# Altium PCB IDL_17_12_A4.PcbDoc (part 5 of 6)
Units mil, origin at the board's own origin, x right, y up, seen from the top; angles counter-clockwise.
Board outline 3172.06 x 10350 mil, 6 copper layers (Top Signal, Mid Signal, 3.3 Volt, GND, 5 Volt, Bot Signal), stack 122.8 mil thick; 332 components, 120 nets, 1937 pads, 197 vias.
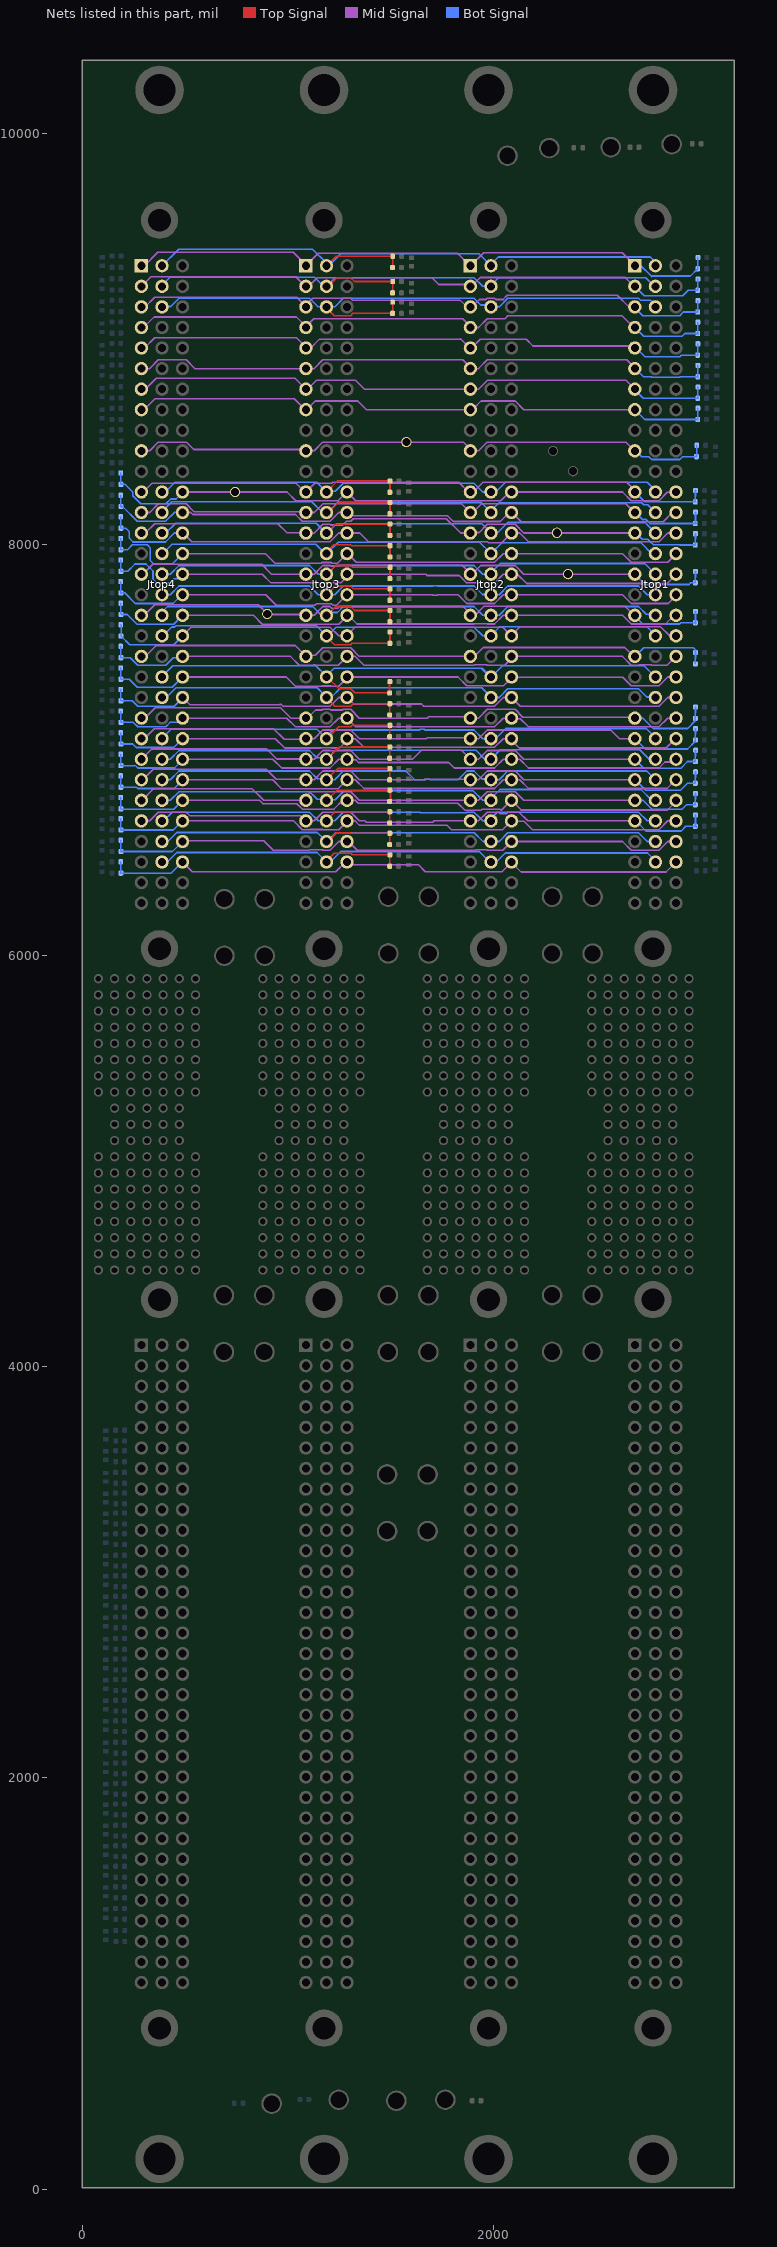
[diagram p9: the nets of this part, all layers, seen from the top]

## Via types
v1: diameter 25.59, hole 12, Top Signal to Bot Signal, 197 vias

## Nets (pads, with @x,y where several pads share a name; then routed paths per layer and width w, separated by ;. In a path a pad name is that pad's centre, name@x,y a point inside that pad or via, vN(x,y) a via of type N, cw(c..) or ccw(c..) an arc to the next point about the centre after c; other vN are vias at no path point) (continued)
JT3: Jtop1.A28 Jtop2.A28 Jtop3.A28 Jtop4.A28 R1R_IDL_17_12_TerA3.1 R2R_IDL_17_12_TerA3.2 | length 2896
  Mid Signal w8: Jtop4.A28@288.16,6654.97 328.09,6654.97 370.57,6697.45 505.76,6697.45 522.36,6680.84 1060,6680.84 1085.51,6655.33 Jtop3.A28@1088.16,6654.97 1128.09,6654.97 1170.57,6697.45 1305.76,6697.45 1348.24,6654.97 1375.92,6654.97 1382.07,6648.82 1705.13,6648.82 1709.63,6653.31 ; 1709.63,6654.97 Jtop2.A28@1888.16,6654.97 1928.09,6654.97 1970.57,6697.45 2025.56,6697.45 2032.55,6690.46 2063.58,6690.46 2070.57,6697.45 2125.04,6697.45 2167.52,6654.97 Jtop1.A28@2688.16,6654.97
  Bot Signal w8: Jtop1.A28@2692.51,6655.52 2741.96,6606.08 2913.68,6606.08 2936.14,6628.54 R1R_IDL_17_12_TerA3.1@2982.45,6628.54 ; R2R_IDL_17_12_TerA3.2@2983.33,6683.56 2983.33,6629.92 2983.58,6629.67 R1R_IDL_17_12_TerA3.1@2988.3,6624.96
JT4: Jtop1.A27 Jtop2.A27 Jtop3.A27 Jtop4.A27 R1R_IDL_17_12_TerA4.1 R2R_IDL_17_12_TerA4.2 | length 2901.7
  Mid Signal w8: Jtop4.A27@288.16,6754.97 286.98,6750.7 289.7,6753.42 348.47,6812.19 825.23,6812.19 882.73,6754.69 1067.76,6754.69 1078.1,6765.03 1110.52,6797.45 1305.76,6797.45 1348.24,6754.97 Jtop2.A27@1888.16,6754.97 1928.09,6754.97 1970.57,6797.45 2105.76,6797.45 2148.24,6754.97 2677.39,6754.97 2682.78,6760.35 Jtop1.A27@2684.55,6762.12
  Bot Signal w8: Jtop1.A27@2688.16,6754.97 2728.08,6754.97 2771.32,6711.73 2917.65,6711.73 ; 2917.4,6711.49 2917.65,6711.73 ; R2R_IDL_17_12_TerA4.2@2983.33,6788.56 2983.33,6760.61 2982.45,6759.73 R1R_IDL_17_12_TerA4.1@2982.45,6733.54 2939.45,6733.54 2917.65,6711.73
JT5: Jtop1.A26 Jtop2.A26 Jtop3.A26 Jtop4.A26 R1R_IDL_17_12_TerA5.1 R2R_IDL_17_12_TerA5.2 | length 2896.1
  Mid Signal w8: Jtop4.A26@288.16,6854.97 294.49,6854.97 345.59,6906.06 894.94,6906.06 943.77,6857.23 Jtop3.A26@1085.38,6857.23 ; Jtop3.A26@1088.16,6854.97 1128.09,6854.97 1170.57,6897.45 1305.76,6897.45 1348.24,6854.97 1380.4,6854.97 ; 1380.4,6855.02 1380.4,6854.97 ; Jtop2.A26@1883.24,6854.97 1880.13,6858.07 1669.4,6858.07 1666.3,6854.97 1380.4,6854.97 ; Jtop2.A26@1888.16,6854.97 1928.09,6854.97 1970.57,6897.45 2105.76,6897.45 2148.24,6854.97 Jtop1.A26@2688.16,6854.97 2688.86,6854.97 Jtop1.A26@2691.33,6857.43 ; Jtop1.A26@2685.24,6860.17 Jtop1.A26@2688.16,6860.17
  Bot Signal w8: Jtop1.A26@2690.58,6855.61 2741.45,6804.73 2910.48,6804.73 2944.28,6838.54 R1R_IDL_17_12_TerA5.1@2982.45,6838.54 2982.45,6864.73 2983.33,6865.61 R2R_IDL_17_12_TerA5.2@2983.33,6893.56
JT6: Jtop1.A25 Jtop2.A25 Jtop3.A25 Jtop4.A25 R1R_IDL_17_12_TerA6.1 R2R_IDL_17_12_TerA6.2 | length 2939.3
  Mid Signal w8: Jtop4.A25@288.16,6954.97 338.14,7004.95 897.38,7004.95 946.22,6956.12 1080.5,6956.12 1084.91,6951.71 1085.38,6951.23 Jtop3.A25@1086.39,6952.59 ; Jtop3.A25@1088.16,6954.96 Jtop3.A25@1086.39,6952.59 ; Jtop2.A25@1887.34,6960.37 1890.45,6957.26 1892.74,6954.97 1928.08,6954.97 1970.57,6997.45 2105.76,6997.45 2148.24,6954.97 Jtop1.A25@2688.16,6954.97 ; Jtop2.A25@1888.16,6954.97 1844.97,6998.16 1650.22,6998.16 1607.03,6954.97 1348.24,6954.97 1305.76,6997.45 1270.57,6997.45 1268.44,6995.32 1207.88,6995.32 1205.76,6997.45 1170.57,6997.45 1128.08,6954.97 1093.64,6954.97 1091.27,6952.59 1088.16,6952.59 Jtop3.A25@1086.39,6952.59
  Bot Signal w8: Jtop1.A25@2688.16,6954.97 2731.4,6911.73 2912.48,6911.73 2944.28,6943.54 R1R_IDL_17_12_TerA6.1@2982.45,6943.54 2982.45,6969.73 2983.33,6970.61 R2R_IDL_17_12_TerA6.2@2983.33,6998.56
JT7: Jtop1.A24 Jtop2.A24 Jtop3.A24 Jtop4.A24 R1R_IDL_17_12_TerA7.1 R2R_IDL_17_12_TerA7.2 | length 2909.7
  Mid Signal w8: Jtop4.A24@288.16,7054.97 302.03,7054.97 350.96,7103.9 930.7,7103.9 982.99,7051.6 1085.95,7051.6 Jtop3.A24@1088.16,7054.97 1128.09,7054.97 1170.57,7097.45 1305.76,7097.45 1348.44,7054.77 1674.53,7054.77 1678.65,7058.88 1884.24,7058.88 Jtop2.A24@1888.16,7054.97 1928.09,7054.97 1970.57,7097.45 2570.77,7097.45 2613.25,7054.97 Jtop1.A24@2688.16,7054.97 ; Jtop1.A24@2688.16,7054.97 Jtop1.A24@2688.33,7055.09
  Bot Signal w8: Jtop1.A24@2688.16,7054.97 2738.4,7004.73 2944.28,7004.73 2982.45,7042.91 R1R_IDL_17_12_TerA7.1@2982.45,7048.54 2982.45,7074.73 2983.33,7075.61 R2R_IDL_17_12_TerA7.2@2983.33,7103.56
JT8: Jtop1.A23 Jtop2.A23 Jtop3.A23 Jtop4.A23 R1R_IDL_17_12_TerA8.1 R2R_IDL_17_12_TerA8.2 | length 2932.4
  Mid Signal w8: Jtop4.A23@288.16,7154.96 304.84,7154.96 355.11,7205.24 964.87,7205.24 1015.22,7154.89 Jtop3.A23@1088.16,7154.97 Jtop3.A23@1089.27,7154.89 ; Jtop3.A23@1090.74,7154.89 Jtop3.A23@1089.27,7154.89 ; Jtop1.A23@2688.16,7154.97 2688.98,7159.85 2688.16,7159.85 2143.35,7159.85 2105.76,7197.45 1970.57,7197.45 1928.08,7154.96 Jtop2.A23@1888.16,7154.96 1881.92,7161.2 1684.6,7161.2 1678.37,7154.96 1348.24,7154.96 1305.76,7197.45 1270.57,7197.45 1267.16,7194.04 1209.16,7194.04 1205.76,7197.45 1170.57,7197.45 1167.16,7194.04 1135.22,7194.04 1092.15,7150.97 1089.27,7148.09 Jtop3.A23@1089.27,7154.89
  Bot Signal w8: Jtop1.A23@2688.16,7154.97 2728.08,7154.97 2778.32,7104.73 2945.28,7104.73 2982.45,7141.91 R1R_IDL_17_12_TerA8.1@2982.45,7153.54 2982.45,7179.73 2983.33,7180.61 R2R_IDL_17_12_TerA8.2@2983.33,7208.56
JT9: Jtop1.A20 Jtop2.A20 Jtop3.A20 Jtop4.A20 R1R_IDL_17_12_TerA9.1 R2R_IDL_17_12_TerA9.2 | length 2907
  Mid Signal w8: Jtop4.A20@288.16,7454.97 306.48,7454.97 359.78,7508.26 1035.73,7508.26 1087.01,7456.98 Jtop3.A20@1088.16,7454.97 1095.67,7454.97 1095.67,7460.01 1133.13,7460.01 1170.57,7497.45 1305.76,7497.45 1348.24,7454.97 Jtop2.A20@1888.16,7454.97 1906.95,7454.97 1950.47,7498.48 2639.52,7498.48 2685.6,7452.4 2685.73,7452.27 Jtop1.A20@2688.16,7454.97
  Bot Signal w8: Jtop1.A20@2688.16,7454.97 2730.93,7497.73 2972.33,7497.73 2983.33,7486.73 R2R_IDL_17_12_TerA9.2@2983.33,7473.56 2983.33,7445.61 2982.45,7444.73 R1R_IDL_17_12_TerA9.1@2982.45,7418.54
JT10: AS.1 Jtop1.A18 Jtop2.A18 Jtop3.A18 Jtop4.A18 R1R_IDL_17_12_TerA10.1 R2R_IDL_17_12_TerA10.2 | length 2889.6
  Mid Signal w8: Jtop4.A18@288.16,7654.97 302.48,7654.97 353.55,7706.04 857.11,7706.04 900.92,7662.23 904.17,7658.98 1084.89,7658.98 Jtop3.A18@1086.77,7657.09 ; Jtop3.A18@1088.16,7654.97 1128.09,7654.97 1170.57,7697.45 1205.76,7697.45 1213.72,7689.48 1242.78,7689.48 1250.75,7697.45 1853.99,7697.45 Jtop2.A18@1892.32,7659.12 ; Jtop2.A18@1888.16,7654.97 1911.32,7654.97 1954.84,7698.49 2640.49,7698.49 2686.08,7652.89 2686.54,7652.44 Jtop1.A18@2688.16,7654.97
  Bot Signal w8: Jtop1.A18@2692.73,7645.68 2725.92,7612.49 2905.76,7612.49 2911.81,7618.54 R1R_IDL_17_12_TerA10.1@2982.45,7618.54 ; R1R_IDL_17_12_TerA10.1@2982.26,7613.16 2983.33,7614.22 2983.33,7618.54 R2R_IDL_17_12_TerA10.2@2983.33,7673.56
JT11: DTACK.1 Jtop1.A16 Jtop2.A16 Jtop3.A16 Jtop4.A16 R1R_IDL_17_12_TerA11.1 R2R_IDL_17_12_TerA11.2 | length 2900.5
  Mid Signal w8: Jtop4.A16@288.16,7854.97 294.33,7854.97 342.51,7903.14 873.03,7903.14 920.95,7855.23 1088.16,7855.23 Jtop3.A16@1088.67,7855.23 ; Jtop3.A16@1088.16,7854.96 1128.08,7854.96 1170.57,7897.45 1205.76,7897.45 1208.35,7894.85 1247.35,7894.85 1251.5,7899 1849.15,7899 1888.47,7859.69 Jtop2.A16@1888.16,7854.97 1889.28,7853.85 1889.28,7848.03 1889.53,7848.03 1892.31,7850.82 1938.94,7897.45 2105.76,7897.45 2148.24,7854.97 2363.44,7854.97 Jtop1.A16@2688.16,7854.97
  Bot Signal w8: Jtop1.A16@2688.16,7854.97 2738.4,7804.73 2951.28,7804.73 2960.08,7813.54 R1R_IDL_17_12_TerA11.1@2982.45,7813.54 2982.45,7839.73 2983.33,7840.61 R2R_IDL_17_12_TerA11.2@2983.33,7868.56
JT12: Jtop1.A14 Jtop2.A14 Jtop3.A14 Jtop4.A14 R1R_IDL_17_12_TerA12.1 R2R_IDL_17_12_TerA12.2 WRITE.1 | length 2922.4
  Mid Signal w8: Jtop4.A14@288.16,8054.96 307.22,8054.96 352.78,8100.52 951.76,8100.52 996.25,8056.03 Jtop3.A14@1086.28,8056.03 ; Jtop3.A14@1085.53,8054.61 Jtop3.A14@1086.28,8054.61 ; Jtop3.A14@1086.38,8056.03 Jtop3.A14@1086.28,8056.03 ; Jtop1.A14@2688.16,8054.97 2308.92,8054.97 2148.24,8054.97 2105.76,8097.45 1970.57,8097.45 1930.56,8057.44 1888.54,8057.44 Jtop2.A14@1888.16,8054.96 1887.96,8055.16 1841.08,8055.16 1771.29,8124.96 1318.23,8124.96 1305.76,8112.48 1285.6,8112.48 1267.63,8094.51 1208.69,8094.51 1205.76,8097.45 1170.57,8097.45 1127.73,8054.61 1088.16,8054.61 Jtop3.A14@1086.28,8054.61 ; Jtop3.A14@1086.28,8054.61 1086.28,8054.97 Jtop3.A14@1086.28,8056.03
  Bot Signal w8: Jtop1.A14@2688.96,8059.36 2690.75,8057.56 2723.75,8024.57 2751.44,8024.57 2771.28,8004.73 ; 2763.18,8013.08 2778.82,7997.45 2905.76,7997.45 2906.45,7996.75 R1R_IDL_17_12_TerA12.1@2982.09,7996.75 2982.09,8023.73 2982.96,8024.61 R2R_IDL_17_12_TerA12.2@2982.96,8051.77
JT13: Jtop1.A13 Jtop2.A13 Jtop3.A13 Jtop4.A13 R1R_IDL_17_12_TerA13.1 R2R_IDL_17_12_TerA13.2 | length 2885.2
  Mid Signal w8: Jtop4.A13@288.16,8154.97 328.09,8154.97 370.57,8197.45 505.76,8197.45 543.83,8159.38 Jtop3.A13@1083.49,8159.38 ; Jtop3.A13@1088.16,8154.97 1128.08,8154.97 1171.04,8197.92 1844.66,8197.92 1885.01,8157.57 Jtop2.A13@1888.16,8154.97 1899.58,8154.97 1942.53,8197.92 2643.47,8197.92 2687.3,8154.1 2690.15,8151.25 Jtop1.A13@2688.16,8154.97
  Bot Signal w8: Jtop1.A13@2687.17,8159.71 2690.04,8156.84 2726.82,8120.07 2731.78,8120.07 2733.44,8121.72 2741.73,8121.72 2761.7,8101.75 R1R_IDL_17_12_TerA13.1@2982.09,8101.75 ; R2R_IDL_17_12_TerA13.2@2982.96,8156.77 2982.96,8105.07 2984.18,8103.85 R1R_IDL_17_12_TerA13.1@2987.02,8101.01
JT14: Jtop1.A12 Jtop2.A12 Jtop3.A12 Jtop4.A12 R1R_IDL_17_12_TerA14.1 R2R_IDL_17_12_TerA14.2 | length 2954.8
  Mid Signal w8: Jtop4.A12@288.16,8254.97 296.99,8254.97 339.71,8297.68 1040.35,8297.68 1081.49,8256.55 1081.49,8254.97 Jtop3.A12@1088.16,8254.97 1130.64,8297.45 1213.36,8297.45 1218.21,8302.29 1831.29,8302.29 1878.62,8254.97 Jtop2.A12@1888.16,8254.97 1901.47,8254.97 1949.08,8302.57 2648.75,8302.57 2688.45,8262.87 2688.45,8258.73 2688.16,8258.73 2658.28,8258.73 2658.28,8254.97 Jtop1.A12@2688.16,8254.97
  Bot Signal w8: Jtop1.A12@2693.2,8255.79 2692.31,8256.68 Jtop1.A12@2688.16,8254.97 2690.57,8253.16 2736.98,8206.75 R1R_IDL_17_12_TerA14.1@2982.09,8206.75 2982.09,8233.73 2982.96,8234.61 R2R_IDL_17_12_TerA14.2@2982.96,8261.77
JT15: Jtop1.A10 Jtop2.A10 Jtop3.A10 Jtop4.A10 R1R_IDL_17_12_TerA15.1 R2R_IDL_17_12_TerA15.2 SYSCLK.1 | length 2896
  Mid Signal w8: Jtop4.A10@288.16,8454.97 328.09,8454.97 370.57,8497.45 505.76,8497.45 542.01,8461.19 1088.16,8461.19 Jtop3.A10@1091.62,8461.19 ; Jtop3.A10@1088.16,8454.97 1128.09,8454.97 1170.57,8497.45 1576.8,8497.45 1854.18,8497.45 1892.41,8459.22 Jtop2.A10@1896.66,8454.97 ; Jtop2.A10@1888.16,8454.97 Jtop2.A10@1896.66,8454.97 ; Jtop1.A10@2688.16,8454.97 2686.54,8454.87 2643.96,8497.45 1970.57,8497.45 1928.09,8454.97 Jtop2.A10@1896.66,8454.97
  Bot Signal w8: Jtop1.A10@2689.55,8459.56 2691.15,8457.96 2722.42,8426.69 2756.36,8426.69 2770.57,8412.49 2905.76,8412.49 2919.96,8426.69 R1R_IDL_17_12_TerA15.1@2988.09,8426.69 ; R1R_IDL_17_12_TerA15.1@2983.06,8427.04 2985.4,8429.38 2988.97,8432.95 R2R_IDL_17_12_TerA15.2@2988.97,8481.71
JT16: Jtop1.A8 Jtop2.A8 Jtop3.A8 Jtop4.A8 R1R_IDL_17_12_TerA16.1 R2R_IDL_17_12_TerA16.2 | length 2905.5
  Mid Signal w8: Jtop4.A8@288.16,8654.97 300.95,8654.97 354.37,8708.38 1031.35,8708.38 1082.75,8656.98 1082.75,8654.97 Jtop3.A8@1088.16,8654.97 1090.64,8654.98 1133.11,8697.45 1340.78,8697.45 1383.26,8654.97 Jtop2.A8@1888.16,8654.97 ; Jtop2.A8@1878.28,8662.46 1888.16,8662.46 1905.25,8662.46 1940.23,8697.45 2105.76,8697.45 2148.24,8654.97 Jtop1.A8@2685.63,8654.97 ; Jtop1.A8@2686.69,8653.91 Jtop1.A8@2685.63,8654.97 ; Jtop1.A8@2688.16,8654.97 Jtop1.A8@2685.63,8654.97
  Bot Signal w8: Jtop1.A8@2688.61,8654.97 2736.2,8607.39 R1R_IDL_17_12_TerA16.1@2993.79,8607.39 ; R1R_IDL_17_12_TerA16.1@2993.99,8606.13 2994.52,8606.67 2994.67,8606.82 2994.67,8607.39 R2R_IDL_17_12_TerA16.2@2994.67,8662.41
JT17: Jtop1.A7 Jtop2.A7 Jtop3.A7 Jtop4.A7 R1R_IDL_17_12_TerA17.1 R2R_IDL_17_12_TerA17.2 | length 2902.4
  Mid Signal w8: Jtop4.A7@288.16,8754.97 307.37,8754.97 360.36,8807.95 1034.91,8807.95 1086.19,8756.67 Jtop3.A7@1088.16,8754.96 1088.16,8750.34 1091.95,8750.34 1092.37,8750.76 1139.05,8797.45 1330.64,8797.45 1373.12,8754.97 Jtop2.A7@1888.16,8754.97 1928.09,8754.97 1970.57,8797.45 2645.91,8797.45 2688.28,8755.08 Jtop1.A7@2688.83,8754.52
  Bot Signal w8: Jtop1.A7@2687.7,8751.74 2729.05,8710.39 R1R_IDL_17_12_TerA17.1@2993.79,8710.39 ; Jtop1.A7@2688.16,8754.97 Jtop1.A7@2689.54,8753.59 ; R2R_IDL_17_12_TerA17.2@2994.67,8765.41 2994.67,8712.72 2995.4,8711.99 R1R_IDL_17_12_TerA17.1@2996.73,8710.66
JT18: Jtop1.A6 Jtop2.A6 Jtop3.A6 Jtop4.A6 R1R_IDL_17_12_TerA18.1 R2R_IDL_17_12_TerA18.2 | length 2898.3
  Mid Signal w8: Jtop4.A6@288.16,8854.97 328.09,8854.97 370.57,8897.45 505.76,8897.45 548.24,8854.97 1072.35,8854.97 Jtop3.A6@1080.07,8862.69 ; Jtop3.A6@1088.16,8854.97 1128.09,8854.97 1170.57,8897.45 1850.68,8897.45 1890.66,8857.46 1892.34,8855.78 Jtop2.A6@1888.16,8854.97 1928.09,8854.97 1970.57,8897.45 2648.15,8897.45 2689.39,8856.2 Jtop1.A6@2692.77,8852.82
  Bot Signal w8: Jtop1.A6@2688.16,8854.97 2690.71,8854.58 2729.9,8815.39 2767.66,8815.39 2770.57,8812.49 2905.76,8812.49 2908.66,8815.39 R1R_IDL_17_12_TerA18.1@2993.79,8815.39 ; R2R_IDL_17_12_TerA18.2@2994.67,8870.41 2994.67,8815.39 2994.67,8813.15 R1R_IDL_17_12_TerA18.1@2996.39,8811.43
JT19: Jtop1.A5 Jtop2.A5 Jtop3.A5 Jtop4.A5 R1R_IDL_17_12_TerA19.1 R2R_IDL_17_12_TerA19.2 | length 2965.7
  Mid Signal w8: Jtop4.A5@288.16,8954.96 302.98,8954.96 352.41,9004.4 1042.13,9004.4 1084.75,8961.78 1088.16,8961.78 Jtop3.A5@1088.16,8954.97 1111.23,8954.97 1154.75,8998.49 1840.54,8998.49 ; 1839.68,8999.34 1840.54,8998.49 ; Jtop2.A5@1883.28,8955.74 1840.54,8998.49 ; Jtop2.A5@1885.12,8954.23 1840.86,8998.49 1840.54,8998.49 ; Jtop2.A5@1888.16,8954.97 Jtop2.A5@1893.82,8954.97 ; Jtop2.A5@1890.63,8951.78 1890.99,8952.14 Jtop2.A5@1893.82,8954.97 ; Jtop1.A5@2689.05,8953.4 2687.82,8954.63 2677.94,8964.52 2192.44,8964.52 2159.51,8997.45 1936.3,8997.45 Jtop2.A5@1893.82,8954.97
  Bot Signal w8: Jtop1.A5@2688.16,8954.97 2689.28,8953.84 2692.51,8957.07 2737.1,8912.49 2905.76,8912.49 2913.66,8920.39 R1R_IDL_17_12_TerA19.1@2993.79,8920.39 2993.79,8946.73 2994.67,8947.61 R2R_IDL_17_12_TerA19.2@2994.67,8975.41
JT20: Jtop1.A4 Jtop2.A4 Jtop3.A4 Jtop4.A4 R1R_IDL_17_12_TerA20.1 R2R_IDL_17_12_TerA20.2 | length 2916
  Mid Signal w8: Jtop4.A4@288.16,9054.97 298.59,9054.97 349.73,9106.1 1042,9106.1 1087.97,9060.13 1125.58,9097.73 1851.15,9097.73 Jtop2.A4@1889.2,9059.69 ; Jtop3.A4@1088.16,9054.97 Jtop3.A4@1096.88,9054.97 ; Jtop2.A4@1888.16,9054.97 1889.77,9054.8 1927.92,9054.8 1970.57,9097.45 2056.22,9097.45 2070.46,9111.69 2625.92,9111.69 2682.64,9054.97 Jtop1.A4@2688.16,9054.97
  Bot Signal w8: Jtop1.A4@2688.16,9054.97 2731.4,9011.73 2917.62,9011.73 2931.28,9025.39 R1R_IDL_17_12_TerA20.1@2993.79,9025.39 ; R2R_IDL_17_12_TerA20.2@2994.67,9080.41 2994.67,9025.39 2994.67,9024.42 R1R_IDL_17_12_TerA20.1@2996.39,9022.7
JT21: Jtop1.A3 Jtop2.A3 Jtop3.A3 Jtop4.A3 R1R_IDL_17_12_TerA21.1 R2R_IDL_17_12_TerA21.2 | length 2912
  Mid Signal w8: Jtop4.A3@288.16,9154.97 305.32,9154.97 352.35,9202 1043.31,9202 1084.03,9161.27 1086.13,9161.81 1121.77,9197.45 1305.76,9197.45 1316.63,9186.57 1839.68,9186.57 1871.29,9154.97 Jtop2.A3@1888.16,9154.97 1890.17,9152.96 1894.23,9152.96 1932.41,9191.14 1964.26,9191.14 1970.57,9197.45 2005.76,9197.45 2012.06,9191.14 2046.63,9191.14 2067.57,9212.07 2602.49,9212.07 2659.6,9154.97 Jtop1.A3@2688.16,9154.97
  Bot Signal w8: Jtop1.A3@2685.32,9153.06 2685.79,9152.59 2725.9,9112.49 2905.76,9112.49 2923.66,9130.39 R1R_IDL_17_12_TerA21.1@2993.79,9130.39 ; R1R_IDL_17_12_TerA21.1@2990.99,9130.59 2992.3,9131.89 2994.67,9134.26 R2R_IDL_17_12_TerA21.2@2994.67,9185.41
JT22: Jtop1.A2 Jtop2.A2 Jtop3.A2 Jtop4.A2 R1R_IDL_17_12_TerA22.1 R2R_IDL_17_12_TerA22.2 | length 2903.5
  Mid Signal w8: Jtop4.A2@288.16,9254.97 335.03,9301.83 1038.05,9301.83 1085.34,9254.54 Jtop3.A2@1088.16,9254.97 1101.34,9254.97 1143.82,9297.45 1701.44,9297.45 1734.95,9263.94 1879.91,9263.94 1887.65,9256.2 Jtop2.A2@1888.16,9254.97 1891.1,9252.03 1936.85,9297.78 2640.99,9297.78 2683.26,9255.51 Jtop1.A2@2688.16,9254.97
  Bot Signal w8: Jtop1.A2@2688.16,9254.97 2734.4,9208.73 2921.28,9208.73 2947.94,9235.39 R1R_IDL_17_12_TerA22.1@2993.79,9235.39 2993.79,9261.73 2994.67,9262.61 R2R_IDL_17_12_TerA22.2@2994.67,9290.41
JT23: Jtop1.A1 Jtop2.A1 Jtop3.A1 Jtop4.A1 R1R_IDL_17_12_TerA23.1 R2R_IDL_17_12_TerA23.2 | length 2959.5
  Mid Signal w8: Jtop4.A1@288.16,9354.97 302.73,9354.97 368.01,9420.25 1027.26,9420.25 Jtop3.A1@1090.35,9357.16 ; Jtop3.A1@1088.16,9354.97 Jtop3.A1@1090.35,9357.16 ; Jtop3.A1@1093.28,9354.23 Jtop3.A1@1090.35,9357.16 ; Jtop2.A1@1883.61,9362.84 1877.87,9362.84 1825.25,9415.47 1148.66,9415.47 Jtop3.A1@1090.35,9357.16 ; Jtop2.A1@1888.16,9354.97 1889.13,9354.97 1952.5,9418.34 2626.1,9418.34 Jtop1.A1@2687.34,9357.1
  Bot Signal w8: Jtop1.A1@2688.16,9354.97 2717.17,9354.97 2767.13,9305 ; 2769.83,9302.3 2767.13,9305 ; R1R_IDL_17_12_TerA23.1@2989.2,9335.57 2993.91,9340.28 2994.67,9341.04 R2R_IDL_17_12_TerA23.2@2994.67,9395.41 ; R1R_IDL_17_12_TerA23.1@2993.79,9340.39 2958.4,9305 2767.13,9305
JT24: Jtop1.B30 Jtop2.B30 Jtop3.B30 Jtop4.B30 R1R_IDL_17_12_TerA24.1 R2R_IDL_17_12_TerA24.2 | length 2957.4
  Top Signal w8: Jtop3.B30@1188.16,6454.97 1184.01,6455.89 1185.62,6457.51 1225.56,6497.45 1305.76,6497.45 1313.55,6489.66 R2R_IDL_17_12_TerA24.2@1496.47,6489.66 1496.47,6438.65 1498.04,6437.08 1500.39,6434.74 R1R_IDL_17_12_TerA24.1@1495.59,6434.64
  Bot Signal w8: Jtop4.B30@388.16,6454.97 413.7,6454.97 459.99,6501.26 1142.38,6501.26 1181.3,6462.33 1181.3,6459.73 1164.28,6459.73 1164.28,6454.97 Jtop3.B30@1188.16,6454.97 1206.81,6454.97 1258.29,6506.44 1930.55,6506.44 1981.36,6455.63 1981.36,6454.97 Jtop2.B30@1988.16,6454.97 2013.92,6454.97 2057.58,6498.62 2749.38,6498.62 2788.47,6459.54 Jtop1.B30@2788.16,6454.97
JT25: Jtop1.B29 Jtop2.B29 Jtop3.B29 Jtop4.B29 R1R_IDL_17_12_TerA25.1 R2R_IDL_17_12_TerA25.2 | length 2941.6
  Top Signal w8: Jtop3.B29@1189.42,6548.4 1192.08,6551.05 1238.47,6597.45 1305.76,6597.45 1308.55,6594.66 R2R_IDL_17_12_TerA25.2@1496.47,6594.66 1496.47,6539.64 1496.47,6538.57 R1R_IDL_17_12_TerA25.1@1491.04,6533.14
  Bot Signal w8: Jtop4.B29@388.16,6554.97 416.35,6554.97 460.13,6598.74 1143.19,6598.74 1181.3,6560.63 1181.3,6554.97 Jtop3.B29@1188.16,6554.97 1191.93,6557.6 1231.77,6597.45 1907.5,6597.45 1949.98,6554.97 Jtop2.B29@1988.16,6554.97 1987.28,6555.85 Jtop2.B29@1987.28,6563.06 ; Jtop1.B29@2788.16,6554.97 2748.24,6554.97 2705.76,6597.45 2070.57,6597.45 2028.09,6554.97 1995.37,6554.97 1991.77,6558.57 Jtop2.B29@1987.28,6563.06 ; Jtop2.B29@1987.28,6563.06 1987.28,6570.93 1979.41,6570.93 Jtop2.B29@1987.28,6563.06
JT26: Jtop1.B28 Jtop2.B28 Jtop3.B28 Jtop4.B28 R1R_IDL_17_12_TerA26.1 R2R_IDL_17_12_TerA26.2 | length 2898.9
  Top Signal w8: Jtop3.B28@1185,6654.67 1186.72,6656.4 1229.98,6699.66 R2R_IDL_17_12_TerA26.2@1496.47,6699.66 1496.47,6653.18 1500.3,6649.35 R1R_IDL_17_12_TerA26.1@1503.34,6646.31
  Bot Signal w8: Jtop4.B28@394.24,6654.12 437.57,6697.45 1105.76,6697.45 1148.24,6654.97 Jtop3.B28@1188.16,6654.97 ; Jtop3.B28@1188.36,6655.78 1188.67,6655.47 1189.18,6654.97 1228.09,6654.97 1245.68,6672.56 1270.57,6697.45 1641.31,6697.45 1644.92,6693.84 1676.45,6693.84 1678.05,6695.44 1696.93,6695.44 1697.48,6694.89 1868.01,6694.89 1870.56,6697.45 1905.76,6697.45 1930.64,6672.56 1948.24,6654.97 Jtop2.B28@1988.16,6654.97 ; Jtop2.B28@1978.33,6656.61 Jtop2.B28@1982.42,6660.71 ; Jtop2.B28@1982.42,6660.71 2019.16,6697.45 2705.76,6697.45 2748.24,6654.97 Jtop1.B28@2788.16,6654.97
JT27: Jtop1.B27 Jtop2.B27 Jtop3.B27 Jtop4.B27 R1R_IDL_17_12_TerA27.1 R2R_IDL_17_12_TerA27.2 | length 2909.2
  Top Signal w8: Jtop3.B27@1193.36,6758.99 1239.03,6804.66 R2R_IDL_17_12_TerA27.2@1496.47,6804.66 1499.9,6801.23 1499.9,6752.1 R1R_IDL_17_12_TerA27.1@1495.59,6749.64
  Bot Signal w8: Jtop4.B27@388.16,6754.97 428.08,6754.97 470.57,6797.45 1105.76,6797.45 1130.64,6772.56 1142.97,6760.23 1186.28,6760.23 1186.28,6756.85 Jtop3.B27@1188.16,6754.97 1187.61,6757.6 1188.16,6757.6 1230.72,6757.6 1274.96,6801.85 1901.36,6801.85 1948.24,6754.97 Jtop2.B27@1988.16,6754.97 1988.16,6763.73 1991.13,6763.73 1991.13,6766.35 2032.17,6807.39 2718.12,6807.39 2770.55,6754.97 Jtop1.B27@2788.16,6754.97
JT28: Jtop1.B26 Jtop2.B26 Jtop3.B26 Jtop4.B26 R1R_IDL_17_12_TerA28.1 R2R_IDL_17_12_TerA28.2 | length 2917.4
  Top Signal w8: Jtop3.B26@1187.53,6860.55 1189.42,6860.09 1192.38,6859.36 1242.67,6909.66 R2R_IDL_17_12_TerA28.2@1496.47,6909.66 1496.47,6863.31 R1R_IDL_17_12_TerA28.1@1494.98,6861.82
  Bot Signal w8: Jtop4.B26@388.16,6854.97 428.08,6854.97 470.56,6897.45 1105.76,6897.45 1142.65,6860.55 Jtop3.B26@1187.53,6860.55 ; Jtop3.B26@1188.16,6854.96 1228.08,6854.96 1270.57,6897.45 1574.43,6897.45 1615.94,6855.94 1667.27,6855.94 1669.4,6858.07 1688.28,6858.07 1690.42,6855.94 1829.06,6855.94 1870.57,6897.45 1905.76,6897.45 1944.31,6858.89 Jtop2.B26@1986.65,6858.89 ; Jtop2.B26@1988.16,6854.97 2028.08,6854.97 2070.56,6897.45 2746.38,6897.45 2788.51,6855.31 Jtop1.B26@2790.76,6853.06
JT29: Jtop1.B25 Jtop2.B25 Jtop3.B25 Jtop4.B25 R1R_IDL_17_12_TerA29.1 R2R_IDL_17_12_TerA29.2 | length 2917.7
  Top Signal w8: Jtop3.B25@1188.16,6954.97 1190.41,6954.32 1248.57,7012.49 1305.76,7012.49 1307.93,7014.66 R2R_IDL_17_12_TerA29.2@1496.47,7014.66 1497.93,7012.38 1495.59,7010.05 R1R_IDL_17_12_TerA29.1@1495.59,6959.64
  Bot Signal w8: Jtop4.B25@388.16,6954.97 428.08,6954.97 470.57,6997.45 1105.76,6997.45 1141.37,6961.84 1188.16,6961.84 Jtop3.B25@1188.16,6954.97 1190.49,6954.73 1233.91,6998.16 1915.42,6998.16 1915.68,6997.9 1958.62,6954.97 Jtop2.B25@1976.28,6954.97 ; Jtop2.B25@1988.16,6954.97 Jtop2.B25@1976.28,6954.97 ; Jtop1.B25@2788.16,6954.97 2758.15,6954.97 2712.25,7000.87 2034.13,7000.87 1993.09,6959.83 1993.09,6957.73 1988.16,6957.73 1976.28,6957.73 Jtop2.B25@1976.28,6954.97
JT30: Jtop1.B24 Jtop2.B24 Jtop3.B24 Jtop4.B24 R1R_IDL_17_12_TerA30.1 R2R_IDL_17_12_TerA30.2 | length 2943.4
  Top Signal w8: Jtop3.B24@1188.16,7054.97 1188.93,7053.71 1189.17,7053.96 1247.7,7112.48 1305.76,7112.48 1312.93,7119.66 R2R_IDL_17_12_TerA30.2@1496.47,7119.66 1496.47,7064.64 1496.47,7057.67 R1R_IDL_17_12_TerA30.1@1495.96,7057.16
  Bot Signal w8: Jtop4.B24@388.16,7054.97 394.28,7061.08 394.28,7063.14 393.93,7063.14 432.04,7101.26 1141.87,7101.26 1182.42,7060.71 Jtop3.B24@1176.68,7054.97 ; Jtop3.B24@1182.42,7060.71 1218.21,7096.5 1269.62,7096.5 1270.57,7097.45 1641.99,7097.45 1644.9,7100.36 1663.78,7100.36 1666.69,7097.45 1905.76,7097.45 1948.24,7054.97 Jtop2.B24@1988.16,7054.97 2010.06,7054.97 2059.53,7104.44 2743.52,7104.44 2786.52,7061.45 2788.16,7061.45 Jtop1.B24@2788.16,7054.97 ; Jtop3.B24@1188.16,7054.97 Jtop3.B24@1176.68,7054.97 ; Jtop3.B24@1176.68,7054.97 1174.67,7054.97 1174.67,7052.96 Jtop3.B24@1176.68,7054.97
JT31: Jtop1.B22 Jtop2.B22 Jtop3.B22 Jtop4.B22 R1R_IDL_17_12_TerA31.1 R2R_IDL_17_12_TerA31.2 | length 2896.6
  Top Signal w8: Jtop3.B22@1191.39,7249.05 1227.96,7212.49 1305.76,7212.49 1317.93,7224.66 R2R_IDL_17_12_TerA31.2@1496.47,7224.66 1496.47,7171.29 1496.86,7170.9 1498.42,7169.34 R1R_IDL_17_12_TerA31.1@1495.59,7169.64
  Bot Signal w8: Jtop4.B22@388.16,7254.97 409.22,7254.97 456.12,7301.86 1143.19,7301.86 1181.3,7263.75 1181.3,7259.73 1183.39,7259.73 Jtop3.B22@1188.16,7254.97 1209.78,7254.97 1257.4,7302.58 1943.86,7302.58 1989.82,7256.62 Jtop2.B22@1990.3,7256.14 ; Jtop2.B22@1988.16,7254.97 2028.08,7254.97 2070.57,7297.45 2705.76,7297.45 2745.47,7257.73 Jtop1.B22@2784.19,7257.73
JT32: Jtop1.B21 Jtop2.B21 Jtop3.B21 Jtop4.B21 R1R_IDL_17_12_TerA32.1 R2R_IDL_17_12_TerA32.2 | length 3815.8
  Top Signal w8: Jtop3.B21@1193.62,7352.89 1249.07,7297.45 1305.76,7297.45 1325.57,7277.64 R1R_IDL_17_12_TerA32.1@1495.59,7277.64 ; R1R_IDL_17_12_TerA32.1@1495.23,7280.61 R1R_IDL_17_12_TerA32.1@1495.5,7280.89 ; R1R_IDL_17_12_TerA32.1@1498.49,7277.9 1497.17,7279.21 R1R_IDL_17_12_TerA32.1@1495.5,7280.89 ; R1R_IDL_17_12_TerA32.1@1495.5,7280.89 1493.73,7282.66 1493.73,7332.66 R2R_IDL_17_12_TerA32.2@1496.47,7332.66 1496.47,7281.85 R1R_IDL_17_12_TerA32.1@1495.5,7280.89
  Bot Signal w8: Jtop4.B21@388.16,7354.97 388.91,7358.03 441.07,7410.19 1136.17,7410.19 Jtop3.B21@1186.73,7359.63 ; Jtop3.B21@1184.83,7357.73 Jtop3.B21@1185.11,7358.01 ; Jtop3.B21@1188.16,7354.97 1188.16,7358.2 Jtop3.B21@1186.73,7359.63 ; Jtop2.B21@1988.16,7354.97 1945.68,7397.45 1940.72,7397.45 ; Jtop1.B21@2788.16,7354.97 2734.39,7408.74 2043.4,7408.74 1988.9,7354.23 1986.42,7351.75 1985.68,7352.49 1940.72,7397.45 ; Jtop3.B21@1185.11,7358.01 Jtop3.B21@1186.73,7359.63 ; Jtop3.B21@1185.11,7358.01 Jtop3.B21@1186.73,7359.63 ; Jtop3.B21@1186.73,7359.63 1224.55,7397.45 ; Jtop3.B21@1186.73,7359.63 1224.55,7397.45 ; 1224.55,7397.45 1940.72,7397.45 ; 1224.55,7397.45 1224.83,7397.73 1940.44,7397.73 1940.72,7397.45
JT33: Jtop1.B19 Jtop2.B19 Jtop3.B19 Jtop4.B19 R1R_IDL_17_12_TerA33.1 R2R_IDL_17_12_TerA33.2 | length 2902.2
  Top Signal w8: Jtop3.B19@1185.31,7554.32 1186.41,7553.22 1227.15,7512.49 1305.76,7512.49 1311.8,7518.53 R1R_IDL_17_12_TerA33.1@1496.55,7518.53 ; R1R_IDL_17_12_TerA33.1@1496.81,7521.3 1497.43,7521.91 R2R_IDL_17_12_TerA33.2@1497.43,7573.55
  Bot Signal w8: Jtop4.B19@385.95,7548.11 390.48,7552.65 435.57,7597.73 450.73,7597.73 456.58,7603.59 1139.54,7603.59 Jtop3.B19@1188.16,7554.97 ; Jtop3.B19@1190.31,7553.66 1234.09,7597.45 1905.76,7597.45 1948.24,7554.97 Jtop2.B19@1986.45,7554.97 ; Jtop2.B19@1988.16,7554.97 Jtop2.B19@1986.45,7554.97 ; Jtop1.B19@2788.16,7554.97 2788.16,7558.18 2747.86,7598.49 2029.97,7598.49 1987.3,7555.82 Jtop2.B19@1986.45,7554.97
JT34: Jtop1.B18 Jtop2.B18 Jtop3.B18 Jtop4.B18 R1R_IDL_17_12_TerA34.1 R2R_IDL_17_12_TerA34.2 | length 2934.7
  Top Signal w8: Jtop3.B18@1188.16,7654.97 1187.99,7651.61 1189.75,7653.38 1233.82,7697.45 1305.76,7697.45 1324.65,7678.55 R2R_IDL_17_12_TerA34.2@1497.43,7678.55 1497.43,7629.02 1495.92,7627.51 R1R_IDL_17_12_TerA34.1@1496.55,7623.53
  Bot Signal w8: Jtop4.B18@388.16,7654.97 373.87,7654.97 373.87,7655.93 380.53,7662.6 415.38,7697.45 1120.73,7697.45 1163.21,7654.97 Jtop3.B18@1188.16,7654.97 1196.44,7663.25 1196.44,7668.31 1241.43,7668.31 1270.57,7697.45 1905.76,7697.45 1948.24,7654.97 Jtop2.B18@1988.16,7654.97 2028.08,7654.97 2070.57,7697.45 2705.76,7697.45 2743.74,7659.47 2787.04,7659.47 Jtop1.B18@2788.16,7654.97
JT35: Jtop1.B17 Jtop2.B17 Jtop3.B17 Jtop4.B17 R1R_IDL_17_12_TerA35.1 R2R_IDL_17_12_TerA35.2 | length 2913.6
  Top Signal w8: Jtop3.B17@1187.99,7755.15 1230.28,7797.45 1305.76,7797.45 1319.65,7783.55 R2R_IDL_17_12_TerA35.2@1497.43,7783.55 1497.43,7729.54 1497.49,7729.47 R1R_IDL_17_12_TerA35.1@1501.27,7725.69
  Bot Signal w8: Jtop4.B17@388.16,7754.97 428.08,7754.97 470.56,7797.45 1105.76,7797.45 1148.24,7754.97 Jtop3.B17@1188.16,7754.96 ; Jtop3.B17@1191.89,7758.32 1188.54,7754.97 Jtop3.B17@1188.16,7754.96 ; Jtop2.B17@1988.16,7754.97 2028.08,7754.97 2070.56,7797.45 2705.76,7797.45 2748.24,7754.97 Jtop1.B17@2788.16,7754.97 2794.45,7754.97 Jtop1.B17@2796.64,7752.77 ; Jtop2.B17@1989.11,7755.94 1988.16,7755.94 1947.26,7755.94 1905.76,7797.45 1727.36,7797.45 1726.43,7798.38 1707.54,7798.38 1706.61,7797.45 1270.57,7797.45 1228.08,7754.96 Jtop3.B17@1188.16,7754.96
JT36: Jtop1.B16 Jtop2.B16 Jtop3.B16 Jtop4.B16 R1R_IDL_17_12_TerA36.1 R2R_IDL_17_12_TerA36.2 | length 2912.9
  Top Signal w8: Jtop3.B16@1189.51,7852.72 1189.31,7852.62 1185.31,7850.65 1188.89,7854.24 1232.1,7897.44 1305.76,7897.44 1314.65,7888.55 R2R_IDL_17_12_TerA36.2@1497.43,7888.55 1497.43,7833.97 R1R_IDL_17_12_TerA36.1@1501.27,7830.12
  Bot Signal w8: Jtop4.B16@392.29,7855.89 393.22,7854.97 428.09,7854.97 470.56,7897.44 1105.76,7897.44 1148.24,7854.97 Jtop3.B16@1188.16,7854.97 ; Jtop3.B16@1189.31,7852.62 1189.51,7852.72 1189.96,7853.17 1234.24,7897.45 1905.76,7897.45 1948.24,7854.97 Jtop2.B16@1988.16,7854.97 1988.16,7861.29 2033.53,7906.66 2736.47,7906.66 Jtop1.B16@2788.16,7854.97
JT37: Jtop1.B15 Jtop2.B15 Jtop3.B15 Jtop4.B15 R1R_IDL_17_12_TerA37.1 R2R_IDL_17_12_TerA37.2 | length 2897.6
  Top Signal w8: Jtop3.B15@1186.2,7960.44 1223.21,7997.45 1305.76,7997.45 1309.65,7993.55 R2R_IDL_17_12_TerA37.2@1497.43,7993.55 1497.43,7938.53 1497.43,7937.51 R1R_IDL_17_12_TerA37.1@1502.17,7932.77
  Bot Signal w8: Jtop4.B15@395.93,7959.85 437.06,8000.97 1136.17,8000.97 1182.17,7954.97 Jtop3.B15@1188.16,7954.97 ; Jtop3.B15@1193.54,7958.57 1245.79,8010.81 1932.31,8010.81 1932,8011.37 1988.16,7955.21 Jtop2.B15@1988.16,7954.97 ; Jtop2.B15@1992.11,7958.63 2040.55,8007.07 2718.66,8007.07 2770.77,7954.97 Jtop1.B15@2788.16,7954.97
JT38: Jtop1.B14 Jtop2.B14 Jtop3.B14 Jtop4.B14 R1R_IDL_17_12_TerA38.1 R2R_IDL_17_12_TerA38.2 | length 2952.3
  Top Signal w8: Jtop3.B14@1188.16,8054.97 1191.56,8057.73 1232.38,8098.55 R2R_IDL_17_12_TerA38.2@1497.43,8098.55 1497.43,8048.19 1499.32,8046.3 R1R_IDL_17_12_TerA38.1@1506.63,8038.98
  Bot Signal w8: Jtop4.B14@388.16,8054.97 406.8,8054.97 455.11,8103.28 1138.17,8103.28 Jtop3.B14@1182.31,8059.15 ; Jtop3.B14@1185.86,8048.11 1190.44,8052.69 1237.31,8099.56 1843.88,8099.56 1843.98,8099.47 1946.63,8099.47 1989.65,8056.45 Jtop2.B14@1991.14,8054.97 ; Jtop2.B14@1988.16,8054.97 Jtop2.B14@1991.14,8054.97 ; 2745.92,8097.73 2781.96,8061.69 2737.58,8106.07 2069.32,8106.07 2018.21,8054.97 Jtop2.B14@1991.14,8054.97
JT39: Jtop1.B13 Jtop2.B13 Jtop3.B13 Jtop4.B13 R1R_IDL_17_12_TerA39.1 R2R_IDL_17_12_TerA39.2 | length 2984.7
  Top Signal w8: Jtop3.B13@1197.8,8155.91 1245.45,8203.55 R2R_IDL_17_12_TerA39.2@1497.43,8203.55 ; R1R_IDL_17_12_TerA39.1@1496.55,8148.53 1496.55,8202.06 R2R_IDL_17_12_TerA39.2@1497.43,8202.94 ; R1R_IDL_17_12_TerA39.1@1496.81,8146.98 1497.43,8147.6 1497.43,8148.53 R2R_IDL_17_12_TerA39.2@1497.43,8202.94 ; R2R_IDL_17_12_TerA39.2@1502.17,8207.68 1497.73,8203.24 R2R_IDL_17_12_TerA39.2@1497.43,8202.94
  Bot Signal w8: Jtop4.B13@388.16,8154.97 388.16,8162.46 391.92,8162.46 436.05,8206.59 1117.11,8206.59 1168.74,8154.97 Jtop3.B13@1188.16,8154.97 1193.19,8154.97 1242.12,8203.89 1940.55,8203.89 1979.28,8165.16 Jtop2.B13@1979.28,8154.97 ; Jtop2.B13@1988.16,8154.97 Jtop2.B13@1979.86,8154.97 ; Jtop1.B13@2788.41,8154.95 2788.28,8155.08 2750.61,8192.75 2731.18,8192.75 2721.28,8202.65 2027.55,8202.65 1984.01,8159.12 Jtop2.B13@1979.86,8154.97 ; Jtop2.B13@1979.28,8154.97 Jtop2.B13@1979.86,8154.97 ; Jtop2.B13@1979.28,8154.97 1977.95,8154.97 1977.95,8153.05 Jtop2.B13@1979.86,8154.97
JT40: Jtop1.B12 Jtop2.B12 Jtop3.B12 Jtop4.B12 R1R_IDL_17_12_TerA40.1 R2R_IDL_17_12_TerA40.2 | length 2898.4
  Top Signal w8: Jtop3.B12@1194.23,8261.23 1241.55,8308.55 R2R_IDL_17_12_TerA40.2@1497.43,8308.55 1497.43,8253.53 1497.43,8251.69 R1R_IDL_17_12_TerA40.1@1498.6,8250.52
  Bot Signal w8: Jtop4.B12@388.16,8254.97 404.18,8254.97 451.1,8301.88 1141.18,8301.88 1185.32,8257.75 Jtop3.B12@1188.16,8254.97 1190.93,8257.73 1201.86,8257.73 1201.86,8258.24 1231.36,8258.24 1270.57,8297.45 1905.76,8297.45 1948.24,8254.97 Jtop2.B12@1988.16,8254.97 2011.99,8254.97 2058.87,8301.85 2748.02,8301.85 2787.18,8262.69 2787.18,8255.95 Jtop1.B12@2788.16,8254.97
JT41: Jtop1.B3 Jtop2.B3 Jtop3.B3 Jtop4.B3 R1R_IDL_17_12_TerA41.1 R2R_IDL_17_12_TerA41.2 | length 2957.1
  Top Signal w8: Jtop3.B3@1190.76,9147.9 1226.18,9112.49 1305.76,9112.49 1316.77,9123.5 R1R_IDL_17_12_TerA41.1@1509.6,9123.5 ; R2R_IDL_17_12_TerA41.2@1510.47,9178.52 1510.47,9128.02 R1R_IDL_17_12_TerA41.1@1512.27,9126.22
  Bot Signal w8: Jtop4.B3@388.16,9154.96 383.47,9154.96 383.47,9156.98 388.16,9156.98 430.1,9156.98 470.57,9197.45 1105.76,9197.45 1148.24,9154.97 Jtop3.B3@1188.16,9154.97 1228.08,9154.97 1270.57,9197.45 1905.76,9197.45 1939.22,9163.98 1980.81,9163.98 1980.81,9159.73 1988.16,9159.73 2004.28,9159.73 Jtop2.B3@2004.28,9154.97 ; Jtop2.B3@1988.16,9154.97 Jtop2.B3@2004.28,9154.97 ; Jtop1.B3@2788.16,9154.97 2774.28,9154.97 2774.28,9165.16 2785.54,9165.16 2762.51,9188.19 2715.01,9188.19 2705.76,9197.45 2070.57,9197.45 2028.08,9154.97 Jtop2.B3@2004.28,9154.97
JT42: Jtop1.B2 Jtop2.B2 Jtop3.B2 Jtop4.B2 R1R_IDL_17_12_TerA42.1 R2R_IDL_17_12_TerA42.2 | length 2967.9
  Top Signal w8: Jtop3.B2@1187.17,9245.83 1192.23,9250.9 1238.78,9297.45 1305.76,9297.45 1324.69,9278.52 R2R_IDL_17_12_TerA42.2@1510.47,9278.52 1510.47,9227.21 1511.89,9225.79 R1R_IDL_17_12_TerA42.1@1517.03,9220.65
  Bot Signal w8: Jtop4.B2@388.16,9254.97 403.28,9254.97 403.28,9263.59 391.37,9263.59 426.9,9299.12 1129.7,9299.12 1173.86,9254.97 1183.75,9254.97 1183.75,9250.53 Jtop3.B2@1188.16,9254.97 1230.66,9297.45 1905.76,9297.45 1948.24,9254.97 Jtop2.B2@1979.46,9254.97 ; Jtop2.B2@1988.16,9254.97 Jtop2.B2@1982.26,9254.97 ; Jtop1.B2@2788.16,9254.97 2783.67,9254.97 2741.19,9297.45 2024.74,9297.45 1985.21,9257.92 Jtop2.B2@1982.26,9254.97 ; Jtop2.B2@1979.46,9254.97 1979.46,9252.17 Jtop2.B2@1982.26,9254.97 ; Jtop2.B2@1979.46,9254.97 Jtop2.B2@1982.26,9254.97
JT43: Jtop1.B1 Jtop2.B1 Jtop3.B1 Jtop4.B1 R1R_IDL_17_12_TerA43.1 R2R_IDL_17_12_TerA43.2 | length 3629.8
  Top Signal w8: Jtop3.B1@1185.91,9351.59 1188.72,9354.4 1235.81,9401.49 R2R_IDL_17_12_TerA43.2@1510.4,9401.49 1510.4,9346.47 1510.4,9341.85 R1R_IDL_17_12_TerA43.1@1511.99,9340.26
  Bot Signal w8: Jtop4.B1@388.16,9354.97 469.19,9436 1120.49,9436 1184.98,9371.51 1184.98,9358.15 Jtop3.B1@1188.16,9354.97 1199.62,9354.97 1258.22,9413.57 1930.49,9413.57 1984.83,9359.22 2023.34,9397.73 2762.81,9397.73 2784.5,9376.04 2784.5,9354.97 Jtop1.B1@2784.5,9350.54 ; 2070.57,9397.45 2724.78,9397.45
JT44: Jtop1.C30 Jtop2.C30 Jtop3.C30 Jtop4.C30 R1R_IDL_17_12_TerA44.1 R2R_IDL_17_12_TerA44.2 | length 2891.4
  Mid Signal w8: Jtop4.C30@488.16,6454.97 490.25,6453.31 535.31,6408.25 1109.99,6408.25 1110.04,6408.21 1233.82,6408.21 1280.58,6454.97 Jtop3.C30@1284.96,6454.97 ; Jtop3.C30@1288.16,6454.97 Jtop3.C30@1284.96,6454.97 ; 1638.72,6437.63 1634.82,6441.53 1615.94,6441.53 1615.37,6440.97 1298.96,6440.97 1286.56,6453.36 Jtop3.C30@1284.96,6454.97 ; 1639.37,6438.28 1669.3,6408.36 2041.56,6408.36 Jtop2.C30@2087.27,6454.07 ; Jtop2.C30@2088.76,6452.58 2134.82,6406.52 2839.72,6406.52 Jtop1.C30@2888.16,6454.97
  Bot Signal w8: R1R_IDL_17_12_TerA44.1@186.64,6401.78 187.1,6402.24 187.5,6402.63 R2R_IDL_17_12_TerA44.2@187.5,6455.99 ; R1R_IDL_17_12_TerA44.1@188.37,6400.97 432.34,6400.97 Jtop4.C30@485.4,6454.02
JT45: Jtop1.C29 Jtop2.C29 Jtop3.C29 Jtop4.C29 R1R_IDL_17_12_TerA45.1 R2R_IDL_17_12_TerA45.2 | length 2888.7
  Mid Signal w8: Jtop4.C29@490.98,6558 491.17,6559.01 883.12,6559.01 929.65,6512.49 1105.76,6512.49 1108.29,6515.01 1168.04,6515.01 1170.57,6512.49 1205.76,6512.49 1248.24,6554.97 Jtop3.C29@1288.16,6554.97 1297.08,6554.97 1297.08,6553.01 1337.6,6512.49 1913.42,6512.49 1915.07,6514.14 1968.91,6514.14 1970.57,6512.49 2045.68,6512.49 Jtop2.C29@2088.16,6554.97 2628.09,6554.97 2670.57,6512.49 2805.76,6512.49 2848.24,6554.97 2886.95,6554.97 2887.56,6554.36 Jtop1.C29@2888.91,6553.01
  Bot Signal w8: R2R_IDL_17_12_TerA45.2@187.5,6560.99 187.5,6514.54 R1R_IDL_17_12_TerA45.1@192.22,6509.82 ; R1R_IDL_17_12_TerA45.1@188.37,6505.97 438.94,6505.97 488.05,6555.08 Jtop4.C29@490.98,6558
JT46: Jtop1.C28 Jtop2.C28 Jtop3.C28 Jtop4.C28 R1R_IDL_17_12_TerA46.1 R2R_IDL_17_12_TerA46.2 | length 2891.5
  Mid Signal w8: Jtop4.C28@488.16,6654.97 1028.09,6654.97 1070.57,6612.49 1105.76,6612.49 1106.07,6612.8 1170.25,6612.8 1170.57,6612.49 1247.47,6612.49 1289.06,6654.07 Jtop3.C28@1288.16,6654.97 1326.74,6654.97 1346.86,6634.84 ; 1346.86,6633.59 1774.29,6633.59 1796.44,6611.45 2044.64,6611.45 Jtop2.C28@2088.16,6654.97 2088.16,6652.55 2089.16,6653.44 2149.25,6653.44 2190.2,6612.49 2805.76,6612.49 2848.24,6654.97 Jtop1.C28@2888.16,6654.97
  Bot Signal w8: R2R_IDL_17_12_TerA46.2@187.5,6665.99 187.5,6616.49 190.7,6613.29 191.71,6612.28 R1R_IDL_17_12_TerA46.1@188.37,6610.97 442.49,6610.97 487.33,6655.8 488.95,6657.42 Jtop4.C28@488.16,6654.97
JT47: Jtop1.C27 Jtop2.C27 Jtop3.C27 Jtop4.C27 R1R_IDL_17_12_TerA47.1 R2R_IDL_17_12_TerA47.2 | length 3680.4
  Mid Signal w8: Jtop4.C27@488.16,6754.97 862.65,6754.97 880.66,6736.96 882.73,6739.03 1044.02,6739.03 1070.57,6712.49 1224.89,6712.49 ; 1223.49,6711.45 1223.85,6711.45 1224.89,6712.49 ; Jtop2.C27@2088.16,6754.97 2135.39,6707.73 ; Jtop1.C27@2888.16,6754.97 2889.4,6750.6 2846.53,6707.73 ; 1224.89,6712.49 1267.37,6754.97 Jtop3.C27@1288.16,6754.97 1328.44,6754.97 1342.44,6740.97 1827.27,6740.97 1862.12,6706.11 1939.64,6706.11 1944.97,6711.45 2032.58,6711.45 2037.91,6706.11 2087.04,6755.25 2087.74,6754.55 2134.56,6707.73 2135.39,6707.73 ; 2135.39,6707.73 2846.53,6707.73 ; 2135.39,6707.73 2135.61,6707.52 2846.32,6707.52 2846.53,6707.73
  Bot Signal w8: R2R_IDL_17_12_TerA47.2@187.5,6768.99 187.5,6741.61 188.37,6740.73 R1R_IDL_17_12_TerA47.1@188.37,6713.97 188.37,6711.73 444.93,6711.73 Jtop4.C27@488.16,6754.97
JT48: Jtop1.C26 Jtop2.C26 Jtop3.C26 Jtop4.C26 R1R_IDL_17_12_TerA48.1 R2R_IDL_17_12_TerA48.2 | length 2885.2
  Mid Signal w8: Jtop4.C26@488.16,6854.97 926.24,6854.97 969.76,6811.45 1244.47,6811.45 Jtop3.C26@1285.86,6852.84 ; Jtop3.C26@1288.16,6854.97 1291.53,6854.97 1291.53,6852.84 1293.66,6854.97 1328.44,6854.97 1370.93,6812.48 1688.28,6812.48 2005.76,6812.49 2048.24,6854.97 Jtop2.C26@2088.16,6854.97 2128.44,6854.97 2170.92,6812.49 2844.54,6812.49 2887.59,6855.54 Jtop1.C26@2887.73,6855.68
  Bot Signal w8: R2R_IDL_17_12_TerA48.2@187.5,6873.99 187.5,6822.43 189.67,6820.26 R1R_IDL_17_12_TerA48.1@190.96,6818.97 ; R1R_IDL_17_12_TerA48.1@188.37,6818.97 R1R_IDL_17_12_TerA48.1@190.96,6818.97 ; R1R_IDL_17_12_TerA48.1@191.71,6818.21 R1R_IDL_17_12_TerA48.1@190.96,6818.97 ; Jtop4.C26@489.96,6854.23 489.43,6853.7 448.22,6812.49 270.57,6812.49 264.09,6818.97 R1R_IDL_17_12_TerA48.1@190.96,6818.97
JT49: Jtop1.C25 Jtop2.C25 Jtop3.C25 Jtop4.C25 R1R_IDL_17_12_TerA49.1 R2R_IDL_17_12_TerA49.2 | length 2870.6
  Mid Signal w8: Jtop4.C25@488.16,6954.96 Jtop4.C25@493.59,6954.96 ; Jtop4.C25@491.49,6952.86 Jtop4.C25@493.59,6954.96 ; Jtop3.C25@1288.16,6954.96 1248.24,6954.96 1205.76,6912.48 970.05,6912.48 927.57,6954.96 Jtop4.C25@493.59,6954.96 ; Jtop3.C25@1288.67,6952.86 1330.54,6952.86 1344.09,6939.31 1782.47,6939.31 1809.29,6912.49 2005.76,6912.49 2048.24,6954.96 Jtop2.C25@2088.16,6954.96 2128.44,6954.96 2170.92,6912.49 2805.76,6912.49 2834.61,6941.34 Jtop1.C25@2871.93,6941.34
  Bot Signal w8: R1R_IDL_17_12_TerA49.1@187.15,6922.7 187.5,6923.05 187.5,6923.97 R2R_IDL_17_12_TerA49.2@187.5,6978.99 ; R1R_IDL_17_12_TerA49.1@188.37,6923.97 259.09,6923.97 270.57,6912.49 449.31,6912.49 489.97,6953.15 Jtop4.C25@494.02,6957.2
JT50: Jtop1.C24 Jtop2.C24 Jtop3.C24 Jtop4.C24 R1R_IDL_17_12_TerA50.1 R2R_IDL_17_12_TerA50.2 | length 3169.9
  Mid Signal w8: Jtop4.C24@488.16,7054.97 939.57,7054.97 985.22,7009.32 1162.64,7009.32 1164.77,7011.45 1211.56,7011.45 1213.68,7009.32 1251.16,7009.32 1288.99,7047.15 1288.99,7050.73 1308.28,7050.73 Jtop3.C24@1308.28,7054.97 ; Jtop3.C24@1288.16,7054.97 Jtop3.C24@1308.28,7054.97 ; 2638.41,7010.01 2840.7,7010.01 2881.9,7051.22 2840.42,7009.73 2125.34,7009.73 2084.13,7050.94 2080.11,7054.97 2048.24,7054.97 2005.76,7012.48 1370.92,7012.48 1328.44,7054.97 Jtop3.C24@1308.28,7054.97
  Bot Signal w8: R2R_IDL_17_12_TerA50.2@187.5,7083.99 187.5,7056.61 188.37,7055.73 R1R_IDL_17_12_TerA50.1@188.37,7028.97 245.28,7028.97 262.51,7011.73 444.93,7011.73 Jtop4.C24@488.16,7054.97
JT51: Jtop1.C23 Jtop2.C23 Jtop3.C23 Jtop4.C23 R1R_IDL_17_12_TerA51.1 R2R_IDL_17_12_TerA51.2 | length 3356.7
  Mid Signal w8: Jtop4.C23@488.16,7154.97 965.62,7154.97 ; Jtop4.C23@490.76,7151.42 491.23,7151.89 494.3,7154.96 965.63,7154.96 ; Jtop3.C23@1288.16,7154.96 1248.24,7154.96 1205.76,7112.49 1037.83,7112.49 995.35,7154.96 965.63,7154.96 ; Jtop3.C23@1292.48,7149.59 1329.59,7112.48 2005.76,7112.48 2048.24,7154.97 Jtop2.C23@2088.16,7154.97 2087.27,7154.08 2087.55,7153.92 2090.11,7152.43 2130.98,7152.43 2170.92,7112.49 2805.76,7112.49 2848.24,7154.97 Jtop1.C23@2888.16,7154.97
  Bot Signal w8: R2R_IDL_17_12_TerA51.2@187.5,7188.99 187.5,7141.48 R1R_IDL_17_12_TerA51.1@190.7,7138.28 ; R1R_IDL_17_12_TerA51.1@188.37,7133.97 249.08,7133.97 270.57,7112.48 405.76,7112.48 427.24,7133.97 466.38,7133.97 487.77,7155.36 Jtop4.C23@488.95,7156.54
JT52: Jtop1.C22 Jtop2.C22 Jtop3.C22 Jtop4.C22 R1R_IDL_17_12_TerA52.1 R2R_IDL_17_12_TerA52.2 | length 2879.4
  Mid Signal w8: Jtop4.C22@492.57,7250.9 524.23,7219.24 959.07,7219.24 960.73,7220.9 969.02,7220.9 977.43,7212.49 1205.76,7212.49 1248.24,7254.97 Jtop3.C22@1288.16,7254.97 ; Jtop3.C22@1290.21,7255.42 1322.11,7223.53 1650.82,7223.53 1661.86,7212.49 1905.76,7212.49 1906.19,7212.92 1970.13,7212.92 1970.57,7212.49 2005.76,7212.49 2048.24,7254.97 Jtop2.C22@2088.16,7254.97 ; Jtop2.C22@2096.9,7246.38 2130.79,7212.49 2805.76,7212.49 2848.24,7254.97 Jtop1.C22@2888.16,7254.97
  Bot Signal w8: R2R_IDL_17_12_TerA52.2@187.5,7293.99 187.5,7243.94 190.42,7241.02 192.22,7239.22 R1R_IDL_17_12_TerA52.1@188.37,7238.97 244.09,7238.97 270.57,7212.49 448.52,7212.49 489.58,7253.54 489.96,7253.93 Jtop4.C22@488.16,7254.97
JT53: Jtop1.C21 Jtop2.C21 Jtop3.C21 Jtop4.C21 R1R_IDL_17_12_TerA53.1 R2R_IDL_17_12_TerA53.2 | length 2902
  Mid Signal w8: Jtop4.C21@488.16,7354.97 992.3,7354.97 1037.6,7309.66 1162.98,7309.66 1164.77,7311.45 1211.56,7311.45 1213.34,7309.66 1247.38,7309.66 1289.33,7351.62 Jtop3.C21@1288.16,7354.97 1828.08,7354.97 1870.57,7312.48 2049.64,7312.48 2088.72,7351.57 Jtop2.C21@2088.16,7354.97 ; Jtop2.C21@2093.28,7354 2629.05,7354 2670.57,7312.49 2805.76,7312.49 2848.24,7354.97 Jtop1.C21@2888.16,7354.97
  Bot Signal w8: R2R_IDL_17_12_TerA53.2@187.5,7398.99 187.5,7371.61 188.37,7370.73 R1R_IDL_17_12_TerA53.1@188.37,7343.97 229.28,7343.97 268.51,7304.73 437.93,7304.73 Jtop4.C21@488.16,7354.97
JT54: Jtop1.C20 Jtop2.C20 Jtop3.C20 Jtop4.C20 R1R_IDL_17_12_TerA54.1 R2R_IDL_17_12_TerA54.2 | length 2895.1
  Mid Signal w8: Jtop4.C20@488.16,7454.97 1012.9,7454.97 1055.38,7412.49 1123.84,7412.49 1124.46,7413.1 1132.74,7413.1 1133.36,7412.49 1245.6,7412.49 Jtop3.C20@1285.69,7452.57 ; Jtop3.C20@1288.16,7454.97 1328.44,7454.97 1370.92,7412.49 1905.76,7412.49 1906.96,7413.69 1969.37,7413.69 1970.57,7412.49 2054.53,7412.49 2057.08,7415.03 2057.55,7415.03 2092.82,7450.31 Jtop2.C20@2093.28,7450.76 ; Jtop2.C20@2088.16,7454.97 2628.09,7454.97 2670.57,7412.49 2705.76,7412.49 2706.96,7413.69 2769.37,7413.69 2770.57,7412.49 2844.5,7412.49 Jtop1.C20@2887.3,7455.29
  Bot Signal w8: R1R_IDL_17_12_TerA54.1@187.15,7448.7 187.5,7449.05 R2R_IDL_17_12_TerA54.2@187.5,7503.99 ; R1R_IDL_17_12_TerA54.1@188.37,7448.97 234.09,7448.97 270.57,7412.49 405.76,7412.49 442.24,7448.97 488.16,7448.97 490.23,7448.97 Jtop4.C20@490.47,7449.21
JT55: Jtop1.C19 Jtop2.C19 Jtop3.C19 Jtop4.C19 R1R_IDL_17_12_TerA55.1 R2R_IDL_17_12_TerA55.2 | length 2884.9
  Mid Signal w8: Jtop4.C19@488.16,7554.97 489.86,7556.57 529.43,7596.15 880.72,7596.15 882.02,7597.45 1205.76,7597.45 1248.24,7554.97 Jtop3.C19@1288.16,7554.97 ; Jtop3.C19@1291.12,7562 1326.56,7597.45 2045.68,7597.45 Jtop2.C19@2086.3,7556.83 ; Jtop2.C19@2088.16,7554.97 Jtop2.C19@2086.3,7556.83 ; Jtop1.C19@2888.16,7554.97 2858.16,7554.97 2814.65,7598.48 2127.96,7598.48 Jtop2.C19@2086.3,7556.83
  Bot Signal w8: R2R_IDL_17_12_TerA55.2@187.5,7608.99 190.7,7605.78 R1R_IDL_17_12_TerA55.1@190.7,7557.76 ; R1R_IDL_17_12_TerA55.1@188.37,7553.97 231.25,7511.09 445.33,7511.09 Jtop4.C19@484.89,7550.66
JT56: Jtop1.C18 Jtop2.C18 Jtop3.C18 Jtop4.C18 R1R_IDL_17_12_TerA56.1 R2R_IDL_17_12_TerA56.2 | length 2911.2
  Mid Signal w8: Jtop4.C18@488.16,7654.97 833.42,7654.97 876.58,7611.8 1247.26,7611.8 1289.29,7653.83 Jtop3.C18@1288.16,7654.97 1289.4,7653.73 1294.85,7653.73 1294.85,7653.95 1336.32,7612.48 1905.76,7612.48 1906.6,7613.33 1969.72,7613.33 1970.57,7612.48 2005.76,7612.48 2048.24,7654.97 Jtop2.C18@2088.16,7654.97 2628.08,7654.97 2670.57,7612.48 2836.93,7612.48 2883.79,7659.34 Jtop1.C18@2885.28,7660.84 ; Jtop1.C18@2888.16,7654.97 2885.28,7657.85 Jtop1.C18@2885.28,7660.84 ; Jtop1.C18@2885.28,7660.84 2886.16,7661.72 2885.28,7661.72 Jtop1.C18@2885.28,7660.84
  Bot Signal w8: R2R_IDL_17_12_TerA56.2@187.5,7713.99 187.5,7664.94 190.92,7661.52 R1R_IDL_17_12_TerA56.1@193.47,7658.97 ; R1R_IDL_17_12_TerA56.1@195.26,7657.18 R1R_IDL_17_12_TerA56.1@193.47,7658.97 ; Jtop4.C18@488.16,7654.97 444.93,7611.73 267.08,7611.73 219.85,7658.97 R1R_IDL_17_12_TerA56.1@193.47,7658.97
JT57: Jtop1.C17 Jtop2.C17 Jtop3.C17 Jtop4.C17 R1R_IDL_17_12_TerA57.1 R2R_IDL_17_12_TerA57.2 | length 2926.5
  Mid Signal w8: Jtop4.C17@488.16,7754.97 892.29,7754.97 943.77,7703.48 1131.92,7703.48 1139.88,7711.45 1211.56,7711.45 1219.52,7703.48 1236.99,7703.48 Jtop3.C17@1288.31,7754.81 ; Jtop3.C17@1291.43,7751.7 1294.7,7754.97 1705.36,7754.97 1707.54,7752.79 1726.43,7752.79 1728.6,7754.97 1828.09,7754.97 1870.57,7712.49 2005.76,7712.49 2048.24,7754.97 Jtop2.C17@2088.16,7754.97 2628.08,7754.97 2670.57,7712.48 2850.23,7712.48 2890.43,7752.69 2891.79,7754.05 Jtop1.C17@2888.16,7754.97
  Bot Signal w8: R2R_IDL_17_12_TerA57.2@187.5,7818.99 187.5,7763.97 187.5,7761.82 R1R_IDL_17_12_TerA57.1@189.18,7760.14 ; R1R_IDL_17_12_TerA57.1@188.37,7763.97 206.67,7763.97 258.15,7712.49 441.8,7712.49 484.89,7755.58 486.83,7753.64 Jtop4.C17@488.16,7754.97
JT58: Jtop1.C16 Jtop2.C16 Jtop3.C16 Jtop4.C16 R1R_IDL_17_12_TerA58.1 R2R_IDL_17_12_TerA58.2 | length 2982.4
  Mid Signal w8: Jtop4.C16@488.16,7854.96 875.58,7854.96 918.06,7812.48 1258.05,7812.48 1291.75,7846.19 Jtop3.C16@1291.75,7854.96 ; Jtop3.C16@1288.16,7854.96 Jtop3.C16@1291.75,7854.96 ; 1870.31,7812.23 1833.85,7848.7 1677.48,7848.7 1671.21,7854.96 Jtop3.C16@1291.75,7854.96 ; 1870.57,7812.48 2005.76,7812.48 2048.24,7854.96 Jtop2.C16@2088.16,7854.96 2116.81,7854.96 2162.45,7809.33 2845.25,7809.33 2889.53,7853.6 2889.91,7853.99 Jtop1.C16@2888.16,7854.97
  Bot Signal w8: R2R_IDL_17_12_TerA58.2@187.5,7923.99 187.5,7896.61 188.37,7895.73 R1R_IDL_17_12_TerA58.1@188.37,7868.97 221.28,7868.97 257.05,7904.73 310.28,7904.73 344.28,7870.73 344.28,7831.73 364.28,7811.73 426.28,7811.73 447.28,7832.73 488.16,7832.73 Jtop4.C16@488.16,7854.96
JT59: Jtop1.C15 Jtop2.C15 Jtop3.C15 Jtop4.C15 R1R_IDL_17_12_TerA59.1 R2R_IDL_17_12_TerA59.2 | length 2981.6
  Mid Signal w8: Jtop4.C15@488.16,7954.97 891.95,7954.97 938.07,7908.85 1162.17,7908.85 1164.77,7911.45 1211.56,7911.45 1214.15,7908.85 1241.55,7908.85 1282.62,7949.92 1282.62,7954.97 Jtop3.C15@1288.16,7954.97 1292.69,7953.24 1332.58,7913.36 1869.69,7913.36 1870.57,7912.48 2005.76,7912.48 2048.24,7954.97 Jtop2.C15@2088.16,7954.97 2628.08,7954.97 2670.57,7912.48 2848.17,7912.48 2889.41,7953.72 2891.9,7956.21 Jtop1.C15@2888.16,7954.97
  Bot Signal w8: R2R_IDL_17_12_TerA59.2@187.5,8028.99 187.5,8001.61 188.37,8000.73 R1R_IDL_17_12_TerA59.1@188.37,7973.97 220.28,7973.97 244.05,7997.73 316.28,7997.73 331.28,7982.73 331.28,7921.73 348.28,7904.73 437.93,7904.73 Jtop4.C15@488.16,7954.97
JT60: Jtop1.C14 Jtop2.C14 Jtop3.C14 Jtop4.C14 R1R_IDL_17_12_TerA60.1 R2R_IDL_17_12_TerA60.2 | length 2930
  Mid Signal w8: Jtop4.C14@488.16,8054.97 488.54,8056.16 488.94,8055.75 532.21,8012.49 1205.76,8012.49 1248.24,8054.96 Jtop3.C14@1288.16,8054.96 1349.76,8054.96 1392.24,8012.48 1905.76,8012.48 1971.39,8012.49 1976.6,8007.27 2040.57,8007.27 Jtop2.C14@2087.57,8054.28 ; Jtop2.C14@2088.16,8054.97 2128.44,8054.97 2170.92,8012.48 2805.76,8012.48 2848.24,8054.97 2887.42,8054.97 2887.79,8054.6 Jtop1.C14@2887.93,8054.46
  Bot Signal w8: R2R_IDL_17_12_TerA60.2@187.5,8133.99 187.5,8106.61 188.37,8105.73 R1R_IDL_17_12_TerA60.1@188.37,8078.97 212.05,8078.97 228.28,8062.73 228.28,8030.73 247.28,8011.73 405.01,8011.73 448.24,8054.97 Jtop4.C14@488.16,8054.97
JT61: Jtop1.C13 Jtop2.C13 Jtop3.C13 Jtop4.C13 R1R_IDL_17_12_TerA61.1 R2R_IDL_17_12_TerA61.2 | length 2926.3
  Mid Signal w8: Jtop4.C13@491.61,8150.34 492.2,8150.93 496.23,8154.97 528.44,8154.97 538.03,8145.38 1037.67,8145.38 1070.57,8112.49 1205.76,8112.49 1248.24,8154.97 Jtop3.C13@1288.16,8154.97 ; Jtop3.C13@1289.52,8153.96 1308.47,8135 1312.43,8138.96 1777.09,8138.96 1804.6,8111.45 2033.17,8111.45 2076.69,8154.97 Jtop2.C13@2088.16,8154.97 2086.52,8159.38 2089.55,8156.35 2135.32,8110.58 2825.69,8110.58 2870.08,8154.97 Jtop1.C13@2888.16,8154.97
  Bot Signal w8: R2R_IDL_17_12_TerA61.2@187.5,8238.99 187.5,8186.38 189.14,8184.73 R1R_IDL_17_12_TerA61.1@189.91,8183.97 ; R1R_IDL_17_12_TerA61.1@188.37,8183.97 R1R_IDL_17_12_TerA61.1@189.91,8183.97 ; R1R_IDL_17_12_TerA61.1@192.73,8181.15 R1R_IDL_17_12_TerA61.1@189.91,8183.97 ; Jtop4.C13@488.16,8154.97 488.95,8156.29 488.16,8156.29 449.56,8156.29 405.43,8112.16 268.3,8112.16 196.5,8183.97 R1R_IDL_17_12_TerA61.1@189.91,8183.97
JT62: Jtop1.C12 Jtop2.C12 Jtop3.C12 Jtop4.C12 R1R_IDL_17_12_TerA62.1 R2R_IDL_17_12_TerA62.2 SYSRESET.1 | length 2942.6
  Mid Signal w8: Jtop4.C12@488.16,8254.97 743.75,8254.97 995.96,8254.97 1039,8211.92 1244.03,8211.92 Jtop3.C12@1287.47,8255.37 ; Jtop3.C12@1288.16,8254.97 1288.16,8251.25 1291.59,8251.25 1330.92,8211.92 2036.62,8211.92 2079.66,8254.97 Jtop2.C12@2088.16,8254.97 2628.08,8254.97 2670.57,8212.48 2805.76,8212.48 2846.22,8252.95 2888.16,8252.95 2888.92,8252.95 Jtop1.C12@2888.16,8254.97
  Bot Signal w8: R2R_IDL_17_12_TerA62.2@187.5,8346.99 187.5,8319.61 188.37,8318.73 R1R_IDL_17_12_TerA62.1@188.37,8291.97 208.05,8291.97 245.28,8254.73 245.28,8236.45 284.28,8197.45 407.11,8197.45 430.25,8220.59 456.63,8220.59 489.58,8253.54 Jtop4.C12@491.45,8255.41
